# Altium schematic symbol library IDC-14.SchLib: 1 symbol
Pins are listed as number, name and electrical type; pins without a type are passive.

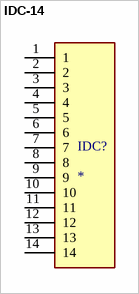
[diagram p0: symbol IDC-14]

## IDC-14
designator IDC?
HEADER, PIN, AMP-LATCH, 14 POS, 2.54 X 2.54, VERTICAL, LOW PROFILE, PCB; MP: 5104338-2; Product_Type: Connector; Centerline_Pitch: 2.54 mm[.1 in]; MF: TE Connectivity; Number_of_Positions: 14
footprint IDC-14
pins: 1, 2, 3, 4, 5, 6, 7, 8, 9, 10, 11, 12, 13, 14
